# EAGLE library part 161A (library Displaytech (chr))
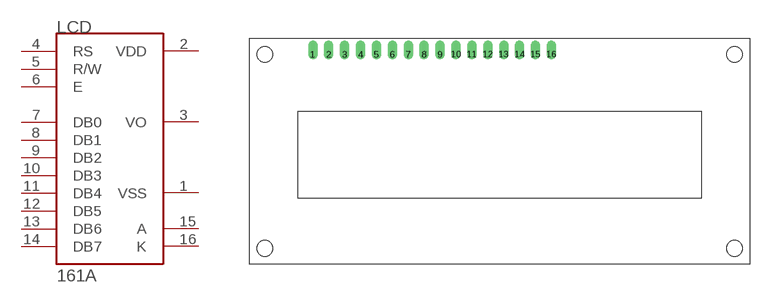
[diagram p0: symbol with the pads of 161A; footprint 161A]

Designator prefix LCD

## 161A  [161A]
1  VSS  pwr
2  VDD  pwr
3  VO  in
4  RS
5  R/W
6  E
7  DB0
8  DB1
9  DB2
10  DB3
11  DB4
12  DB5
13  DB6
14  DB7
15  A  pwr
16  K  pwr

## Footprint 161A (pad centres in mm)
drill 1.016 offset: 1 0,0; 2 2.54,0; 3 5.08,0; 4 7.62,0; 5 10.16,0; 6 12.7,0; 7 15.24,0; 8 17.78,0; 9 20.32,0; 10 22.86,0; 11 25.4,0; 12 27.94,0; 13 30.48,0; 14 33.02,0; 15 35.56,0; 16 38.1,0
